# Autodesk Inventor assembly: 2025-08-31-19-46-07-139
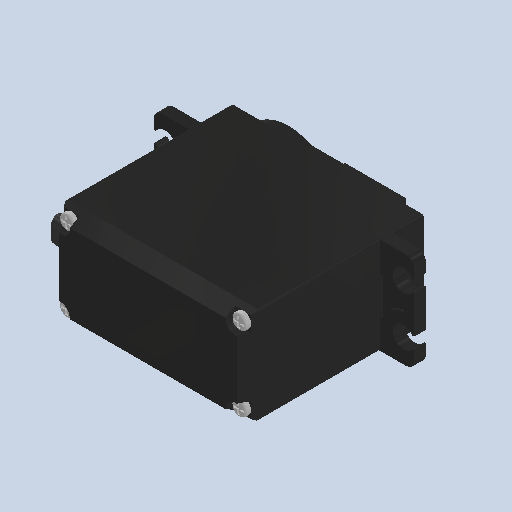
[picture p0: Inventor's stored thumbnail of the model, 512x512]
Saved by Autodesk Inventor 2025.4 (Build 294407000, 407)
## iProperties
Created: 2026-09
Part Number: 2025-08-31-19-46-07-139
Document SubType Name: Assembly
Designer: AdminForWorker
Title: Servo
Author: AdminForWorker
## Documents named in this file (5)
- c:\worker\convert-fusion-r05-cosv3\tmp\job-1\19\temp\files\ca3d996b-dda0-445d-8bee-12a194174ca8\Servo_2.iam
- c:\worker\convert-fusion-r05-cosv3\tmp\job-1\19\temp\files\ca3d996b-dda0-445d-8bee-12a194174ca8\com_top_2.iam
- c:\worker\convert-fusion-r05-cosv3\tmp\job-1\19\temp\files\ca3d996b-dda0-445d-8bee-12a194174ca8\com_but.ipt
- c:\worker\convert-fusion-r05-cosv3\tmp\job-1\19\temp\files\ca3d996b-dda0-445d-8bee-12a194174ca8\Gear.ipt
- c:\worker\convert-fusion-r05-cosv3\tmp\job-1\19\temp\files\ca3d996b-dda0-445d-8bee-12a194174ca8\bolts.ipt
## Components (4 placed, 4 different names)
1. com_top:1 [sub-assembly]
2. com_but:1
3. Gear:1
4. bolts:1
